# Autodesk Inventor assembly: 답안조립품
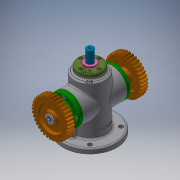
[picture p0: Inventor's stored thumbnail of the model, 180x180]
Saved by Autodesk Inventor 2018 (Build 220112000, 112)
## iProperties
Created: 2020-06
Part Number: 답안조립품
Material: 일반
Document SubType Name: Assembly
Designer: USER
Author: USER
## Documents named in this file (17)
- C:\Users\USER\Desktop\600606V1018\답안조립품.iam
- C:\Users\USER\Desktop\600606V1018\가변스프링.ipt
- C:\Users\USER\Desktop\600606V1018\멈춤링.ipt
- C:\Users\USER\Desktop\600606V1018\베어링 6203.ipt
- C:\Users\USER\Desktop\600606V1018\본체.ipt
- C:\Users\USER\Desktop\600606V1018\볼트 M4.ipt
- C:\Users\USER\Desktop\600606V1018\부시.ipt
- C:\Users\USER\Desktop\600606V1018\스퍼기어.ipt
- C:\Users\USER\Desktop\600606V1018\스프링와셔.ipt
- C:\Users\USER\Desktop\600606V1018\스프링조립용 와셔.ipt
- C:\Users\USER\Desktop\600606V1018\슬라이더.ipt
- C:\Users\USER\Desktop\600606V1018\오일 실 17 30 8.ipt
- C:\Users\USER\Desktop\600606V1018\커버 A.ipt
- C:\Users\USER\Desktop\600606V1018\커버 B.ipt
- C:\Users\USER\Desktop\600606V1018\키 4x4x12.ipt
- C:\Users\USER\Desktop\600606V1018\편심축.ipt
- C:\Users\USER\Desktop\600606V1018\평와셔.ipt
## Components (1 placed, 1 different names)
1. 가변스프링:1
